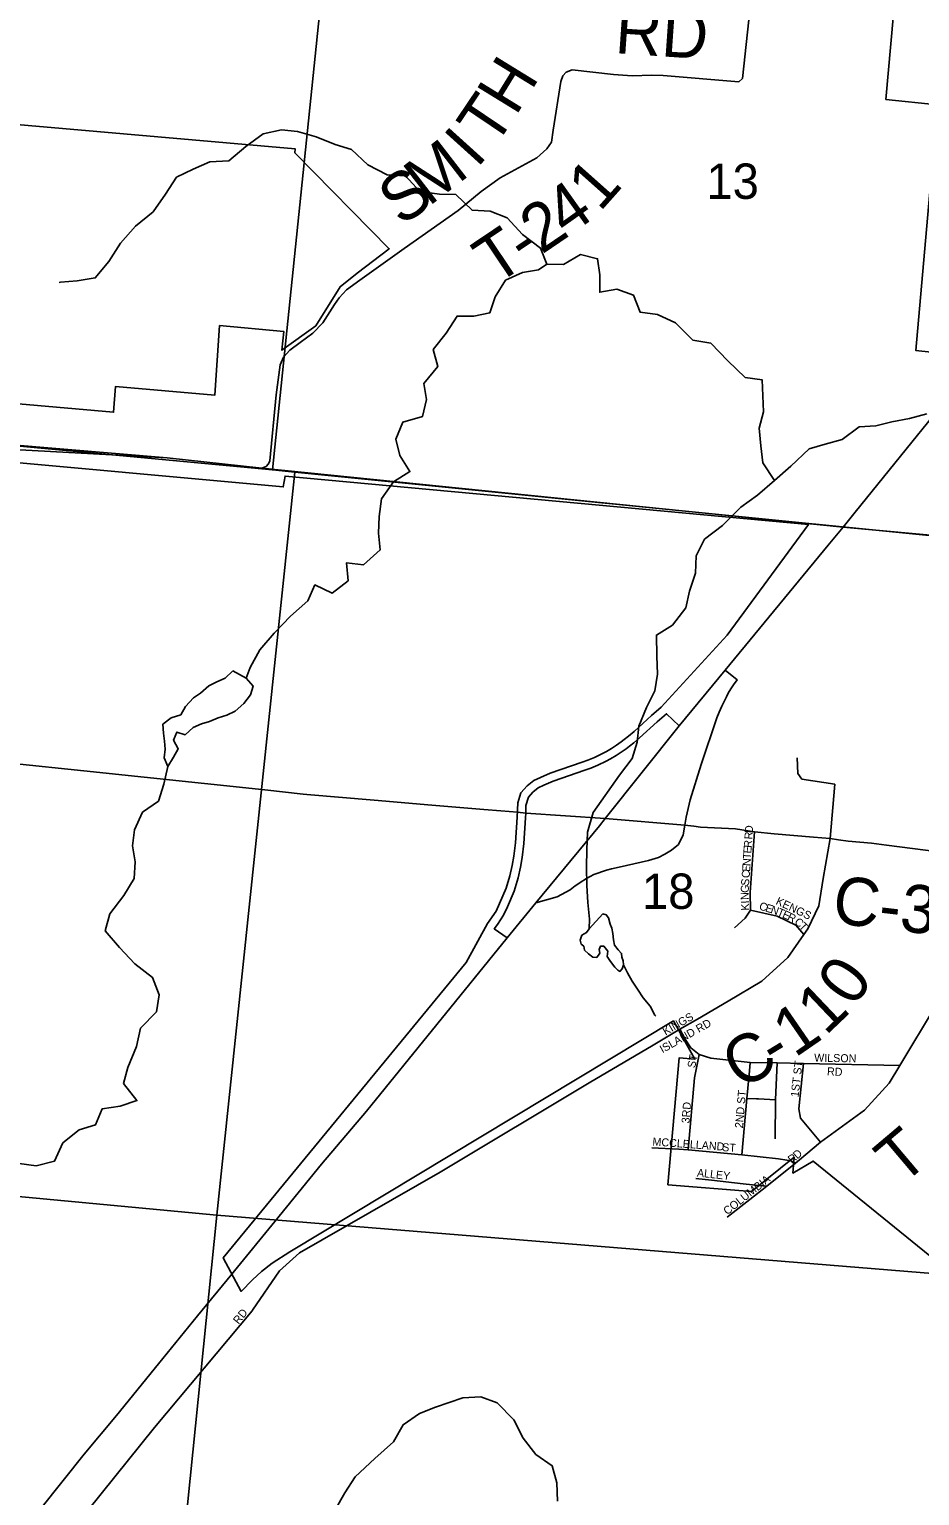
# Model space of a CAD drawing. Extents: x 0 to 34, y -4 to 22.
# Drawn here: x 3.221 to 3.963, y 16.585 to 17.807 of the extents above; entities that cross this region are included whole.
import ezdxf

# ---------------------------------------------------------------- set-up
doc = ezdxf.new("R2010")
doc.units = 0
for name, color, linetype in [('GM_X_City_Street', 7, 'Continuous'), ('GM_X_City_Street_Text', 7, 'Continuous'), ('GM_X_Corporation', 7, 'Continuous'), ('GM_X_County_Road', 7, 'Continuous'), ('GM_X_County_Road_Text', 7, 'Continuous'), ('GM_X_County_Subdivision', 7, 'Continuous'), ('GM_X_Interchange_Ramps', 7, 'Continuous'), ('GM_X_Interstate_Route', 7, 'Continuous'), ('GM_X_Minor_Lake', 7, 'Continuous'), ('GM_X_Minor_River', 7, 'Continuous'), ('GM_X_Section', 7, 'Continuous'), ('GM_X_Section_Text', 7, 'Continuous'), ('GM_X_State_Route', 7, 'Continuous'), ('GM_X_Township', 7, 'Continuous'), ('GM_X_Township_Road', 7, 'Continuous'), ('GM_X_Township_Road_Text', 7, 'Continuous'), ('GM_X_Township_ROW', 7, 'Continuous'), ('GM_X_Township_Subdivision', 7, 'Continuous'), ('GM_X_Township_Subdivision_Text', 7, 'Continuous')]:
    doc.layers.add(name, color=color, linetype=linetype)

msp = doc.modelspace()

# ---------------------------------------------------------------- linework, layer by layer
at = {"layer": 'GM_X_City_Street'}
for points in [[(3.7669, 17.1434), (3.7744, 17.1425)], [(3.7406, 16.9602), (3.7628, 16.9734), (3.7774, 16.9818)], [(3.4062, 16.7388), (3.4065, 16.7392), (3.4291, 16.7721), (3.4458, 16.7872), (3.563, 16.8544), (3.6886, 16.9295), (3.7345, 16.9566)], [(3.8023, 16.8168), (3.8212, 16.8315), (3.8353, 16.8425), (3.8591, 16.8617), (3.8624, 16.8645)], [(3.8521, 16.8643), (3.8553, 16.8638), (3.8591, 16.8617)], [(3.8624, 16.8645), (3.8678, 16.869)], [(3.8287, 16.8432), (3.8353, 16.8425)], [(3.0904, 16.1595), (3.0911, 16.1824), (3.0929, 16.2089), (3.0964, 16.2503), (3.0999, 16.2697), (3.1068, 16.2871), (3.1168, 16.3119), (3.1516, 16.3824), (3.2074, 16.488), (3.2209, 16.5128), (3.2475, 16.5451), (3.325, 16.6415), (3.4062, 16.7388)]]:
    msp.add_lwpolyline(points, dxfattribs=at)
at = {"layer": 'GM_X_Corporation'}
for points in [[(3.9427, 17.8412), (3.9346, 17.7483), (3.9775, 17.7438), (3.9596, 17.5389), (3.9954, 17.5351), (4.0717, 17.6328), (4.1769, 17.7626), (4.1793, 17.7898), (4.2062, 17.7965), (4.2143, 17.8066), (4.255, 17.8481)], [(3.1164, 17.5028), (3.2908, 17.4875), (3.2923, 17.5089), (3.3751, 17.5017), (3.3792, 17.5598), (3.4326, 17.5549), (3.4312, 17.5392), (3.4593, 17.5596), (3.4797, 17.5922), (3.4938, 17.6036), (3.5206, 17.6238), (3.4418, 17.7038), (3.4421, 17.7071), (3.1335, 17.7341)], [(4.0538, 16.7177), (3.8738, 16.8635), (3.857, 16.8535), (3.8582, 16.8667), (3.8225, 16.8381), (3.7529, 16.8438), (3.7621, 16.9495), (3.7753, 16.9484), (3.7574, 16.9803), (3.4376, 16.7878), (3.423, 16.7786), (3.4141, 16.7715), (3.4066, 16.7645), (3.3973, 16.7549), (3.3823, 16.783), (3.5847, 17.0291), (3.6026, 17.0615), (3.6096, 17.0718), (3.6126, 17.0782), (3.618, 17.0909), (3.6212, 17.1013), (3.6231, 17.1099), (3.6244, 17.1176), (3.6258, 17.1288), (3.6271, 17.15), (3.6277, 17.1621), (3.6304, 17.1705), (3.6356, 17.1762), (3.6411, 17.1808), (3.6467, 17.1832), (3.6547, 17.1867), (3.6814, 17.1959), (3.686, 17.1976), (3.6917, 17.1999), (3.6982, 17.2031), (3.7016, 17.2049), (3.7059, 17.2074), (3.71, 17.2101), (3.7139, 17.2128), (3.7165, 17.2148), (3.72, 17.2176), (3.7246, 17.2216), (3.7392, 17.2349), (3.7472, 17.2417), (3.8022, 17.3017), (3.8699, 17.394), (3.4338, 17.4344), (3.4322, 17.4254), (3.1663, 17.4496)]]:
    msp.add_lwpolyline(points, dxfattribs=at)
at = {"layer": 'GM_X_County_Road'}
for points in [[(3.8882, 17.1323), (3.8919, 17.1777)], [(3.7744, 17.1425), (3.7799, 17.1419), (3.8092, 17.1405), (3.8251, 17.1379), (3.8414, 17.1362), (3.8741, 17.1336), (3.8882, 17.1323), (3.8949, 17.1313)], [(3.7774, 16.9818), (3.803, 16.9968), (3.8311, 17.0135), (3.8527, 17.0332), (3.866, 17.0523), (3.8694, 17.0572), (3.8786, 17.0763), (3.8823, 17.0991), (3.8882, 17.1323)], [(3.8949, 17.1313), (3.9032, 17.1301), (3.9224, 17.1284), (3.9351, 17.1268)], [(3.9351, 17.1268), (4.0001, 17.1184), (4.0252, 17.1151), (4.0491, 17.1128)], [(3.7345, 16.9566), (3.7406, 16.9602)]]:
    msp.add_lwpolyline(points, dxfattribs=at)
at = {"layer": 'GM_X_County_Subdivision'}
msp.add_lwpolyline([(3.8919, 17.1777), (3.8646, 17.1819), (3.8611, 17.1864), (3.8606, 17.1997)], dxfattribs=at)
at = {"layer": 'GM_X_Interchange_Ramps'}
for points in [[(3.7669, 17.1434), (3.768, 17.15), (3.7715, 17.1646), (3.7807, 17.1939), (3.7937, 17.2329), (3.7956, 17.2377), (3.7978, 17.2427), (3.7994, 17.2461), (3.8016, 17.2504), (3.8032, 17.2534), (3.8053, 17.2571), (3.8074, 17.2605), (3.8105, 17.2646), (3.8005, 17.2725)], [(3.7623, 17.2262), (3.7518, 17.2363), (3.7439, 17.2296), (3.7293, 17.2163), (3.7245, 17.2122), (3.7208, 17.2092), (3.718, 17.2071), (3.714, 17.2043), (3.7096, 17.2014), (3.705, 17.1988), (3.7015, 17.1968), (3.6945, 17.1935), (3.6886, 17.191), (3.6837, 17.1892), (3.6572, 17.1801), (3.6495, 17.1767), (3.6448, 17.1747), (3.6404, 17.1711), (3.6366, 17.1669), (3.6344, 17.1599), (3.6345, 17.1536)], [(3.6345, 17.1536), (3.6341, 17.1496), (3.6328, 17.1282), (3.6314, 17.1166), (3.63, 17.1085), (3.628, 17.0995), (3.6247, 17.0885), (3.6191, 17.0753), (3.6157, 17.0684), (3.6108, 17.0606), (3.6081, 17.0572), (3.6188, 17.0497)]]:
    msp.add_lwpolyline(points, dxfattribs=at)
at = {"layer": 'GM_X_Interstate_Route'}
for points in [[(3.909, 17.4043), (4.0163, 17.537), (4.2183, 17.7841), (4.2235, 17.7904), (4.2415, 17.8127), (4.2674, 17.841)], [(3.8865, 17.3768), (3.8988, 17.3917), (3.909, 17.4043)], [(3.6957, 17.143), (3.7005, 17.1489), (3.7623, 17.2262), (3.8005, 17.2725), (3.8865, 17.3768)], [(3.6427, 17.0788), (3.6957, 17.143)], [(3.3893, 16.7694), (3.3916, 16.7722), (3.4253, 16.8133), (3.464, 16.861), (3.5017, 16.9051), (3.6188, 17.0497), (3.6427, 17.0788)], [(3, 16.2115), (3.0013, 16.2145), (3.0174, 16.2459), (3.0356, 16.2808), (3.0567, 16.3201), (3.0747, 16.354), (3.0928, 16.3851), (3.1132, 16.4174), (3.1343, 16.4471), (3.1521, 16.4726), (3.1754, 16.505), (3.2031, 16.5413), (3.2301, 16.574), (3.2662, 16.6193), (3.2933, 16.6514), (3.3282, 16.6947), (3.3609, 16.7345), (3.3893, 16.7694)]]:
    msp.add_lwpolyline(points, dxfattribs=at)
at = {"layer": 'GM_X_Minor_Lake'}
for points in [[(3.3632, 17.2534), (3.3575, 17.2497), (3.3507, 17.2424), (3.3468, 17.2355), (3.3387, 17.233), (3.332, 17.2275), (3.3324, 17.2202), (3.3333, 17.2135), (3.3337, 17.2068), (3.333, 17.1996), (3.3361, 17.1923), (3.3408, 17.2002), (3.3447, 17.2071), (3.3408, 17.2142), (3.3436, 17.2211), (3.3505, 17.2188), (3.3573, 17.2248), (3.3641, 17.2279), (3.3708, 17.2299), (3.3781, 17.2328), (3.3851, 17.235), (3.3921, 17.2384), (3.3994, 17.2449), (3.4049, 17.2521), (3.4072, 17.2593), (3.4012, 17.2661), (3.3903, 17.2722)], [(3.3903, 17.2722), (3.3838, 17.2659), (3.377, 17.2628), (3.3703, 17.2597), (3.3632, 17.2534)], [(3.7144, 17.0336), (3.7142, 17.0366), (3.7115, 17.0396), (3.7084, 17.0436), (3.7074, 17.0479), (3.707, 17.0533), (3.706, 17.0576), (3.7047, 17.0611), (3.7032, 17.0662), (3.7014, 17.0687), (3.6987, 17.0695), (3.6872, 17.0572)], [(3.6872, 17.0572), (3.685, 17.054), (3.6812, 17.0517), (3.6796, 17.0477), (3.6806, 17.0444), (3.6827, 17.0425), (3.6834, 17.0393), (3.6866, 17.0363), (3.6903, 17.0335), (3.6935, 17.0332), (3.6962, 17.0369), (3.6955, 17.0399), (3.6966, 17.0425), (3.6995, 17.0425), (3.7027, 17.0384), (3.7023, 17.0341), (3.7049, 17.0298), (3.7086, 17.0252), (3.7112, 17.0227), (3.7128, 17.0216), (3.7147, 17.0237), (3.7159, 17.0272), (3.7156, 17.0304), (3.7144, 17.0336)]]:
    msp.add_lwpolyline(points, dxfattribs=at)
at = {"layer": 'GM_X_Minor_River'}
for points in [[(3.9687, 17.4862), (3.9543, 17.4824), (3.9396, 17.4795), (3.9262, 17.4763), (3.9123, 17.4755), (3.8981, 17.4648), (3.8839, 17.461), (3.8706, 17.457), (3.8553, 17.4426), (3.8417, 17.4308), (3.832, 17.4455), (3.8304, 17.4597), (3.8288, 17.4744), (3.8326, 17.488), (3.8315, 17.5145), (3.8173, 17.5166), (3.8029, 17.5305), (3.7887, 17.545), (3.7737, 17.5476), (3.7593, 17.5621), (3.7443, 17.569), (3.7296, 17.5709), (3.7242, 17.5851), (3.7103, 17.5901), (3.6961, 17.5875), (3.6961, 17.6022), (3.6943, 17.6155), (3.6801, 17.619), (3.6659, 17.6107), (3.652, 17.611), (3.6467, 17.6243), (3.6317, 17.6356), (3.6188, 17.6497), (3.6047, 17.6551), (3.5897, 17.6559), (3.576, 17.669), (3.5624, 17.6692), (3.5461, 17.6714), (3.534, 17.6847), (3.5188, 17.6853), (3.5027, 17.6938), (3.4891, 17.7064), (3.4755, 17.7107), (3.4597, 17.7171), (3.4442, 17.7214), (3.4308, 17.723), (3.4155, 17.7195), (3.4011, 17.7091), (3.3869, 17.697), (3.3711, 17.6962), (3.3572, 17.6901), (3.3433, 17.6834), (3.3342, 17.6693), (3.3238, 17.6546), (3.309, 17.6425), (3.2967, 17.6286), (3.2868, 17.6131), (3.2756, 17.5995), (3.2604, 17.5971), (3.2467, 17.596), (3.2456, 17.5958)], [(3.652, 17.611), (3.6451, 17.6062), (3.6317, 17.604), (3.6175, 17.5976), (3.6089, 17.5837), (3.6044, 17.5704), (3.591, 17.5677), (3.5771, 17.5677), (3.568, 17.5535), (3.5573, 17.5399), (3.561, 17.5257), (3.5493, 17.5116), (3.5517, 17.4982), (3.5482, 17.484), (3.5319, 17.4792), (3.526, 17.4651), (3.5295, 17.4514), (3.5378, 17.4381), (3.5241, 17.4295), (3.5142, 17.4154), (3.5123, 17.4007), (3.5115, 17.3868), (3.5131, 17.3729), (3.499, 17.3603), (3.4851, 17.3622), (3.4864, 17.3472), (3.473, 17.3368), (3.4586, 17.3437), (3.4527, 17.3304), (3.4382, 17.3175), (3.4246, 17.3034), (3.4126, 17.2897), (3.4048, 17.2749), (3.4012, 17.2661)], [(3.8417, 17.4308), (3.8275, 17.4185), (3.8136, 17.4084), (3.7983, 17.3932), (3.7833, 17.3817), (3.7764, 17.368), (3.7759, 17.3536), (3.7708, 17.3386), (3.7678, 17.3245), (3.7566, 17.31), (3.7432, 17.3018), (3.7435, 17.2844), (3.7443, 17.2692), (3.7419, 17.2555), (3.7349, 17.2416), (3.7285, 17.2261), (3.7272, 17.2125), (3.7231, 17.1991), (3.7124, 17.1852), (3.6905, 17.154), (3.6859, 17.1377), (3.6854, 17.123), (3.6849, 17.1088), (3.6854, 17.0933), (3.6862, 17.0791), (3.6875, 17.065), (3.6872, 17.0572)], [(3.3361, 17.1923), (3.3328, 17.1775), (3.3283, 17.1636), (3.3149, 17.1542), (3.3082, 17.1395), (3.3066, 17.1262), (3.3087, 17.1128), (3.3079, 17.0989), (3.2994, 17.0848), (3.2876, 17.0695), (3.2839, 17.0554), (3.2959, 17.0415), (3.3085, 17.0278), (3.3232, 17.0166), (3.3288, 17.0022), (3.3267, 16.988), (3.3133, 16.9744), (3.3098, 16.9589), (3.3026, 16.9415), (3.2991, 16.9281), (3.3103, 16.914), (3.2964, 16.9094), (3.2812, 16.907), (3.2758, 16.8937), (3.2622, 16.8897), (3.2485, 16.8787), (3.2416, 16.8635), (3.2263, 16.8597), (3.2122, 16.8616)], [(3.7159, 17.0272), (3.7192, 17.0204), (3.7231, 17.0136), (3.7275, 17.0069), (3.7322, 16.9995), (3.738, 16.9925), (3.7419, 16.9852), (3.7429, 16.9843)], [(3.6608, 16.5802), (3.6602, 16.5954), (3.6565, 16.6096), (3.6428, 16.6189), (3.6321, 16.6325), (3.6244, 16.6478), (3.6105, 16.6622), (3.5968, 16.667), (3.5819, 16.6662), (3.5591, 16.6585), (3.5457, 16.6531), (3.5321, 16.6438), (3.5241, 16.6296), (3.5085, 16.6157), (3.4922, 16.6005), (3.4837, 16.5871), (3.4754, 16.5729)]]:
    msp.add_lwpolyline(points, dxfattribs=at)
at = {"layer": 'GM_X_Section'}
for points in [[(2.7895, 18.224), (3.4973, 18.1562), (3.4232, 17.4395), (2.7259, 17.5048), (2.7546, 18.0143)], [(3.4973, 18.1562), (4.2059, 18.0856), (4.1349, 17.3684), (3.4418, 17.4375), (3.4232, 17.4395)], [(2.7232, 17.5048), (2.7259, 17.5048), (3.4232, 17.4395), (3.4418, 17.4375), (3.377, 16.8184), (2.662, 16.8858)], [(3.4418, 17.4375), (4.1349, 17.3684), (4.0652, 16.7624), (3.377, 16.8184)], [(2.662, 16.8858), (3.377, 16.8184), (3.3036, 16.0944), (2.5939, 16.1545), (2.6586, 16.8529)]]:
    msp.add_lwpolyline(points, close=True, dxfattribs=at)
msp.add_lwpolyline([(3.3036, 16.0944), (3.377, 16.8184), (4.0652, 16.7624), (4.0634, 16.7403), (4.0672, 16.6915), (4.0602, 16.6759), (4.0527, 16.6613), (4.0438, 16.6439), (4.0347, 16.626), (4.0257, 16.6051), (4.0218, 16.595), (4.016, 16.5736)], dxfattribs=at)
at = {"layer": 'GM_X_State_Route'}
for points in [[(3.4168, 17.1728), (3.2661, 17.1887), (3.2075, 17.1949), (3.1995, 17.1958)], [(3.4519, 17.1691), (3.4488, 17.1694), (3.4168, 17.1728)], [(3.5081, 17.1643), (3.4519, 17.1691)], [(3.5994, 17.1566), (3.556, 17.1602), (3.5081, 17.1643)], [(3.6135, 17.1554), (3.5994, 17.1566)], [(3.6275, 17.1542), (3.6135, 17.1554)], [(3.7005, 17.1489), (3.6345, 17.1536), (3.6275, 17.1542)], [(3.7669, 17.1434), (3.7005, 17.1489)], [(3.7057, 17.107), (3.7123, 17.1085), (3.7366, 17.1141), (3.745, 17.1165), (3.7503, 17.1192), (3.7559, 17.1226), (3.7617, 17.1274), (3.7657, 17.1355), (3.7669, 17.1434)], [(3.6777, 17.0943), (3.6796, 17.0956), (3.6851, 17.0991), (3.6911, 17.1023), (3.7016, 17.1061), (3.7057, 17.107)], [(3.6427, 17.0788), (3.6605, 17.0838), (3.6713, 17.0896), (3.6755, 17.0928), (3.6777, 17.0943)]]:
    msp.add_lwpolyline(points, dxfattribs=at)
at = {"layer": 'GM_X_Township'}
msp.add_lwpolyline([(2.984, 17.4791), (3.3356, 17.4496), (3.4145, 17.4411), (3.8988, 17.3917), (4.1745, 17.3664)], dxfattribs=at)
at = {"layer": 'GM_X_Township_Road'}
for points in [[(3.8297, 17.9023), (3.8149, 17.7658), (3.8119, 17.7629), (3.749, 17.7682), (3.7394, 17.7684), (3.723, 17.7679), (3.7076, 17.769), (3.6731, 17.7728), (3.668, 17.7709), (3.6654, 17.768), (3.6636, 17.7632), (3.6573, 17.7225), (3.6557, 17.7126), (3.6519, 17.707), (3.6437, 17.6996), (3.6129, 17.6828), (3.5971, 17.6714), (3.578, 17.6556), (3.5331, 17.6239), (3.496, 17.5976), (3.4849, 17.5896), (3.4789, 17.5829), (3.4749, 17.5774), (3.4653, 17.5621), (3.4569, 17.5534), (3.4463, 17.5458), (3.4376, 17.5392), (3.4324, 17.5334), (3.4298, 17.5272), (3.4264, 17.502), (3.4212, 17.4472), (3.4205, 17.4457)], [(3.4205, 17.4457), (3.4198, 17.4444), (3.4179, 17.4424), (3.4145, 17.4411), (3.3356, 17.4496), (3.1765, 17.4581), (3.1715, 17.4574)], [(3.8678, 16.869), (3.8801, 16.8792), (3.9168, 16.906), (3.9373, 16.9284), (3.9461, 16.9431), (3.976, 16.9925), (4.0082, 17.043), (4.0491, 17.1128)], [(3.8266, 16.9154), (3.8283, 16.9153), (3.8424, 16.9147)]]:
    msp.add_lwpolyline(points, dxfattribs=at)
at = {"layer": 'GM_X_Township_ROW'}
msp.add_lwpolyline([(3.8422, 16.8821), (3.8424, 16.9147)], dxfattribs=at)
at = {"layer": 'GM_X_Township_Subdivision'}
for points in [[(3.8083, 17.0578), (3.8173, 17.0659), (3.8218, 17.0725), (3.8215, 17.0874), (3.8251, 17.1379)], [(3.8218, 17.0725), (3.844, 17.0675), (3.8594, 17.06), (3.866, 17.0523)], [(3.7628, 16.9734), (3.7672, 16.9652), (3.7719, 16.9579), (3.7789, 16.9523), (3.7887, 16.9493), (3.8214, 16.9457), (3.8438, 16.9453), (3.8659, 16.9449), (3.9461, 16.9431)], [(3.7696, 16.873), (3.7751, 16.9329), (3.7789, 16.9523)], [(3.8145, 16.8688), (3.8187, 16.9157), (3.8208, 16.9387)], [(3.8208, 16.9387), (3.8214, 16.9457)], [(3.8424, 16.9147), (3.8438, 16.9453)], [(3.8801, 16.8792), (3.8634, 16.8992), (3.862, 16.907), (3.8659, 16.9449)], [(3.8187, 16.9157), (3.8266, 16.9154)], [(3.7394, 16.8746), (3.762, 16.8734)], [(3.762, 16.8734), (3.7696, 16.873), (3.8145, 16.8688), (3.8449, 16.8653), (3.8521, 16.8643)], [(3.7762, 16.8491), (3.7893, 16.8476)], [(3.7893, 16.8476), (3.8156, 16.8447)], [(3.8156, 16.8447), (3.8287, 16.8432)]]:
    msp.add_lwpolyline(points, dxfattribs=at)

# ---------------------------------------------------------------- texts
at = {"layer": 'GM_X_City_Street_Text'}
for s, rotation, p in [('KINGS', 30.2553, (3.7509, 16.968)), ('ISLAND RD', 29.3582, (3.7483, 16.9533)), ('R', 35.7381, (3.8558, 16.8612)), ('D', 42.3926, (3.8607, 16.8648)), ('COLUMBIA', 38.4173, (3.8023, 16.8183)), ('RD', 51.3437, (3.395, 16.7271))]:
    msp.add_text(s, height=0.00667, rotation=rotation, dxfattribs=at).set_placement(p)
at = {"layer": 'GM_X_County_Road_Text'}
for s, rotation, p in [('C-31', 353.288, (3.8889, 17.0621)), ('0', 54.5057, (3.9075, 16.9908)), ('1', 43.5784, (3.8842, 16.9675)), ('1', 34.5766, (3.8586, 16.9492)), ('C', 30.5775, (3.8137, 16.9223)), ('-', 31.3815, (3.8426, 16.9393))]:
    msp.add_text(s, height=0.04, rotation=rotation, dxfattribs=at).set_placement(p)
at = {"layer": 'GM_X_Section_Text'}
for s, p in [('13', (3.7849, 17.6654)), ('18', (3.7312, 17.0737))]:
    msp.add_text(s, height=0.02944, rotation=0, dxfattribs=at).set_placement(p)
at = {"layer": 'GM_X_Township_Road_Text'}
for s, rotation, p in [('RD', 356.0551, (3.708, 17.7869)), ('H', 58.4349, (3.626, 17.7337)), ('T', 56.0214, (3.6083, 17.7074)), ('I', 47.9203, (3.5935, 17.6903)), ('M', 37.6977, (3.5534, 17.6585)), ('1', 48.3376, (3.6961, 17.6539)), ('S', 36.3425, (3.5309, 17.6419)), ('4', 35.4081, (3.6687, 17.6331)), ('2', 34.2078, (3.6476, 17.6187)), ('T', 33.9064, (3.6089, 17.5927)), ('-', 33.9615, (3.6338, 17.6095)), ('T', 40.176, (3.9476, 16.8425))]:
    msp.add_text(s, height=0.04, rotation=rotation, dxfattribs=at).set_placement(p)
at = {"layer": 'GM_X_Township_Subdivision_Text'}
for s, rotation, p in [('R', 85.9496, (3.8232, 17.1314)), ('D', 85.9533, (3.8235, 17.1367)), ('T', 85.9508, (3.822, 17.115)), ('E', 85.9508, (3.8223, 17.1197)), ('R', 85.9496, (3.8227, 17.1244)), ('E', 85.9533, (3.8213, 17.1045)), ('N', 85.9507, (3.8216, 17.1092)), ('S', 85.9806, (3.8204, 17.0928)), ('C', 85.9496, (3.8209, 17.0992)), ('G', 87.1572, (3.8201, 17.0869)), ('N', 91.3988, (3.8203, 17.0812)), ('KENGS', 334.5074, (3.8422, 17.0779)), ('I', 92.235, (3.8204, 17.0783)), ('K', 92.2085, (3.8206, 17.0724)), ('C', 344.3082, (3.8284, 17.0732)), ('E', 343.4656, (3.8335, 17.0717)), ('N', 340.7564, (3.8379, 17.0704)), ('T', 337.6303, (3.8433, 17.0685)), ('E', 334.9254, (3.8476, 17.0668)), ('R', 333.7933, (3.8518, 17.0648)), ('C', 322.5084, (3.8577, 17.0617)), ('T', 312.7001, (3.8617, 17.0587)), ('ST', 79.3721, (3.7755, 16.9407)), ('WILSON', 358.9396, (3.8747, 16.9464)), ('1ST ST', 83.371, (3.8617, 16.9166)), ('RD', 356.989, (3.8853, 16.9351)), ('3RD', 85.5949, (3.7708, 16.8948)), ('2ND ST', 85.1332, (3.8153, 16.8907)), ('MCCLELLAND', 355.786, (3.7398, 16.8766)), ('ST', 356.4254, (3.7979, 16.8719)), ('ALLEY', 353.7954, (3.7768, 16.8507))]:
    msp.add_text(s, height=0.00667, rotation=rotation, dxfattribs=at).set_placement(p)

doc.saveas('drawing.dxf')
